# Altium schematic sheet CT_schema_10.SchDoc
size 274 x 160 mm
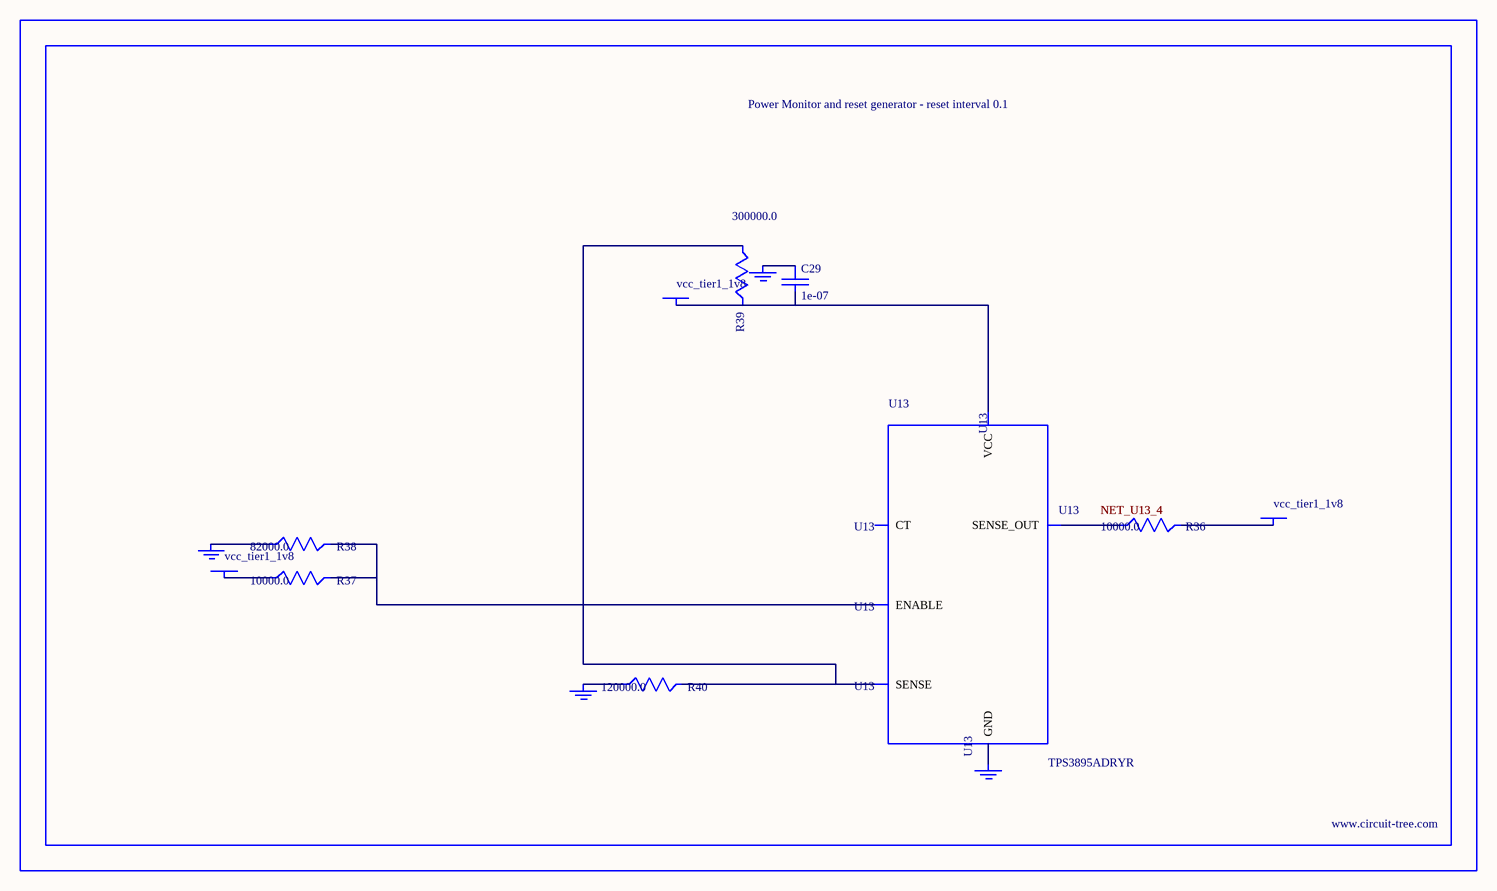
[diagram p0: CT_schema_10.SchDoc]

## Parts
BORDER9  (no value)
C29  1e-07  [C0402]
GND_INSTANCE_9_0  (no value)
GND_INSTANCE_9_1  (no value)
GND_INSTANCE_9_2  (no value)
GND_INSTANCE_9_3  (no value)
POWER_INSTANCE_9_0  vcc_tier1_1v8
POWER_INSTANCE_9_1  vcc_tier1_1v8
POWER_INSTANCE_9_2  vcc_tier1_1v8
R36  10000.0  [R0603]
R37  10000.0  [R0603]
R38  82000.0  [R0603]
R39  300000.0  [R0603]
R40  120000.0  [R0603]
U13  TPS3895ADRYR  [SON-6]

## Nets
NetC29_1: C29.1 GND_INSTANCE_9_2.0(GND)
NetC29_2: C29.2 POWER_INSTANCE_9_2.0(PWR) R39.2 U13.6(VCC)
NetGND_INSTANCE_9_0_0: GND_INSTANCE_9_0.0(GND) R38.1
NetGND_INSTANCE_9_1_0: GND_INSTANCE_9_1.0(GND) R40.1
NetGND_INSTANCE_9_3_0: GND_INSTANCE_9_3.0(GND) U13.2(GND)
NetPOWER_INSTANCE_9_0_0: POWER_INSTANCE_9_0.0(PWR) R37.1
NetPOWER_INSTANCE_9_1_0: POWER_INSTANCE_9_1.0(PWR) R36.2
NetR36_1: R36.1 U13.4(SENSE_OUT)
NetR37_2: R37.2 R38.2 U13.1(ENABLE)
NetR39_1: R39.1 R40.2 U13.3(SENSE)

Not connected (* = marked no-connect by the designer): U13 5(CT)

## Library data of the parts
BORDER9 = BORDER_PAGE9
C29 = C0402C104K3RACTU
GND_INSTANCE_9_0-GND_INSTANCE_9_3 = GND
POWER_INSTANCE_9_0-POWER_INSTANCE_9_2 = PWR
R36 R37 = RC0603JR-0710KL
R38 = RC0603JR-0782KL
R39 = RC0603JR-07300KL
R40 = RC0603JR-07120KL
